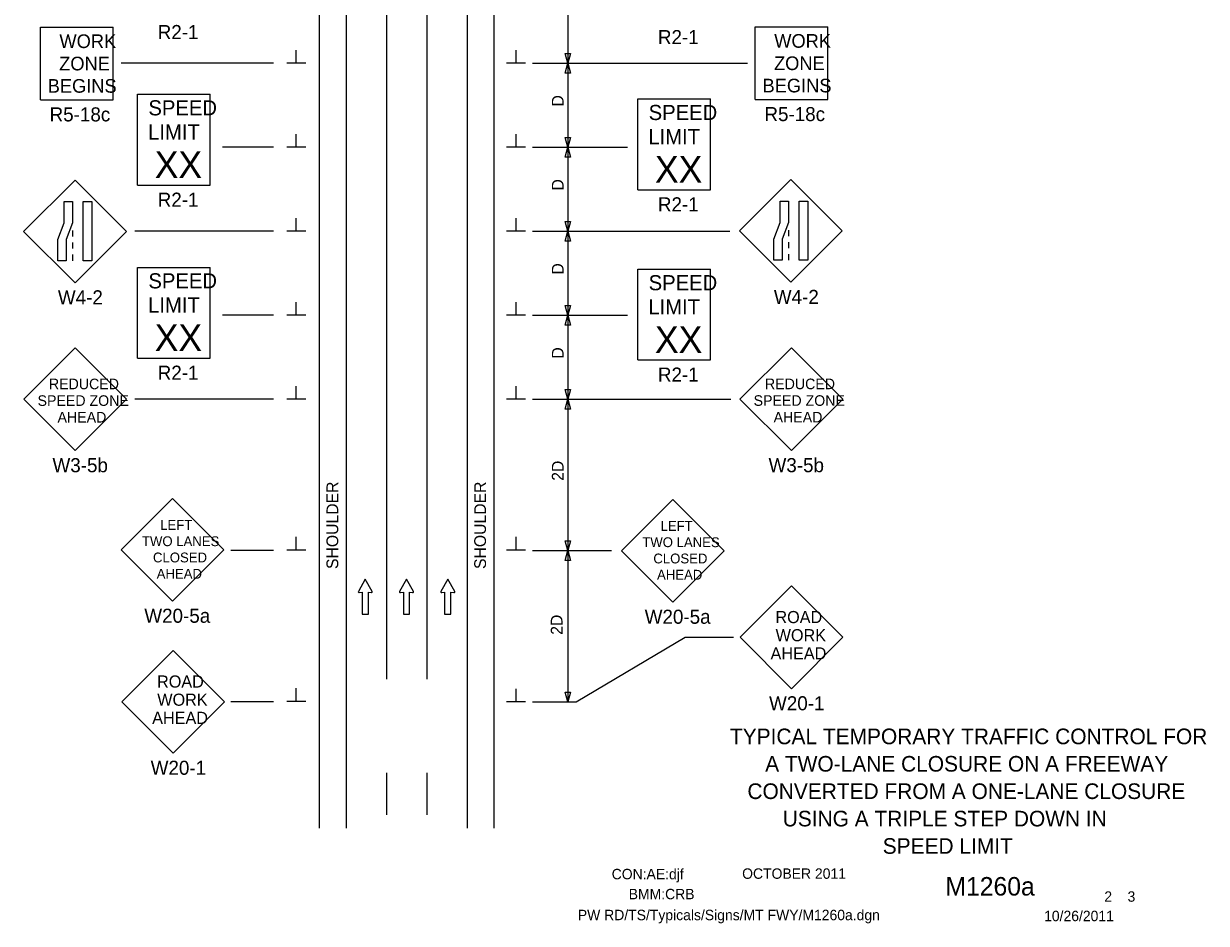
# Model space of a CAD drawing. Extents: x 16503 to 19508, y 5728 to 6974.
# Drawn here: x 17770 to 18473, y 5932 to 6467 of the extents above; entities that cross this region are included whole.
import ezdxf

# ---------------------------------------------------------------- set-up
doc = ezdxf.new("R2010")
doc.units = 0
for name, color, linetype in [('ALI_LEGAL_EX', 7, 'Continuous'), ('BORDER', 7, 'Continuous'), ('BORDER_SIGNAL_WO', 7, 'Continuous'), ('MT_SCRATCH_LEVEL_E', 7, 'Continuous'), ('PAVT_EDGE_EX', 7, 'Continuous'), ('TRAFFIC_SIGNS_PR', 7, 'Continuous'), ('TYPICAL_TEXT_DIMEN_PR', 7, 'Continuous')]:
    doc.layers.add(name, color=color, linetype=linetype)

msp = doc.modelspace()

# ---------------------------------------------------------------- linework, layer by layer
at = {"layer": 'ALI_LEGAL_EX'}
for p, q in [((17985.63, 6921.33), (17985.63, 6077.19)), ((18009.63, 6921.33), (18009.63, 6077.19))]:
    msp.add_line(p, q, dxfattribs=at)
for points in [[(17985.63, 6421.33), (17985.63, 6396.33)], [(18009.63, 6421.33), (18009.63, 6396.33)], [(17985.63, 6321.33), (17985.63, 6296.33)], [(18009.63, 6321.33), (18009.63, 6296.33)], [(17985.63, 6221.33), (17985.63, 6196.33)], [(18009.63, 6221.33), (18009.63, 6196.33)], [(17985.63, 6121.33), (17985.63, 6096.33)], [(18009.63, 6121.33), (18009.63, 6096.33)], [(17985.63, 6021.33), (17985.63, 5996.33)], [(18009.63, 6021.33), (18009.63, 5996.33)]]:
    msp.add_lwpolyline(points, dxfattribs=at)
at = {"layer": 'MT_SCRATCH_LEVEL_E'}
for p, q in [((17973.07, 6136.57), (17968.96, 6129.33)), ((17977.22, 6129.33), (17973.07, 6136.57)), ((17997.6, 6136.57), (17993.49, 6129.33)), ((18001.75, 6129.33), (17997.6, 6136.57)), ((18022.16, 6136.57), (18018.05, 6129.33)), ((18026.31, 6129.33), (18022.16, 6136.57)), ((17969.44, 6128.65), (17971.22, 6128.96)), ((17971.22, 6128.96), (17971.22, 6115.71)), ((17974.96, 6115.71), (17974.96, 6128.96)), ((17974.96, 6128.96), (17976.74, 6128.65)), ((17993.97, 6128.65), (17995.75, 6128.96)), ((17995.75, 6128.96), (17995.75, 6115.71)), ((17999.49, 6115.71), (17999.49, 6128.96)), ((17999.49, 6128.96), (18001.27, 6128.65)), ((18018.53, 6128.65), (18020.31, 6128.96)), ((18020.31, 6128.96), (18020.31, 6115.71)), ((18024.05, 6115.71), (18024.05, 6128.96)), ((18024.05, 6128.96), (18025.83, 6128.65)), ((17971.22, 6115.71), (17974.96, 6115.71)), ((17995.75, 6115.71), (17999.49, 6115.71)), ((18020.31, 6115.71), (18024.05, 6115.71))]:
    msp.add_line(p, q, dxfattribs=at)
for centre, start, end in [((17969.37, 6129.11), 150.42484, 279.96381), ((17976.81, 6129.11), 260.03619, 29.77312), ((17993.9, 6129.11), 150.42484, 279.96381), ((18001.34, 6129.11), 260.03619, 29.77312), ((18018.46, 6129.11), 150.42484, 279.96381), ((18025.9, 6129.11), 260.03619, 29.77312)]:
    msp.add_arc(centre, 0.463, start, end, dxfattribs=at)
at = {"layer": 'PAVT_EDGE_EX'}
for p, q in [((17945.63, 6921.33), (17945.63, 5988.51)), ((17961.63, 6921.33), (17961.63, 5988.51)), ((18033.63, 6921.33), (18033.63, 5988.51)), ((18049.63, 6921.33), (18049.63, 5988.51))]:
    msp.add_line(p, q, dxfattribs=at)
at = {"layer": 'TRAFFIC_SIGNS_PR'}
for p, q in [((17779.88, 6421.85), (17779.88, 6465.05)), ((17779.88, 6465.05), (17823.08, 6465.05)), ((17823.08, 6421.85), (17823.08, 6465.05)), ((18205.13, 6422.03), (18205.13, 6465.23)), ((18205.13, 6465.23), (18248.33, 6465.23)), ((18248.33, 6422.03), (18248.33, 6465.23)), ((17837.58, 6425.1), (17880.78, 6425.1)), ((17837.58, 6371.1), (17837.58, 6425.1)), ((17880.78, 6371.1), (17880.78, 6425.1)), ((17779.88, 6421.85), (17823.08, 6421.85)), ((18135.18, 6422.33), (18178.38, 6422.33)), ((18135.18, 6368.33), (18135.18, 6422.33)), ((18178.38, 6368.33), (18178.38, 6422.33)), ((18205.13, 6422.03), (18248.33, 6422.03)), ((17800.4, 6374.1), (17769.85, 6343.55)), ((17830.95, 6343.55), (17800.4, 6374.1)), ((17837.58, 6371.1), (17880.78, 6371.1)), ((18135.18, 6368.33), (18178.38, 6368.33)), ((18226.32, 6374.35), (18195.77, 6343.8)), ((18256.86, 6343.8), (18226.32, 6374.35)), ((17769.85, 6343.55), (17800.4, 6313)), ((17799, 6344.1), (17799, 6340.5)), ((17800.4, 6313), (17830.95, 6343.55)), ((18195.77, 6343.8), (18226.32, 6313.26)), ((18224.91, 6344.35), (18224.91, 6340.75)), ((18226.32, 6313.26), (18256.86, 6343.8)), ((17799, 6336.9), (17799, 6333.3)), ((18224.91, 6337.15), (18224.91, 6333.55)), ((17799, 6329.7), (17799, 6326.1)), ((18224.91, 6329.95), (18224.91, 6326.35)), ((17837.58, 6322.16), (17880.78, 6322.16)), ((17837.58, 6268.16), (17837.58, 6322.16)), ((17880.78, 6268.16), (17880.78, 6322.16)), ((18135.18, 6321.04), (18178.38, 6321.04)), ((18135.18, 6267.04), (18135.18, 6321.04)), ((18178.38, 6267.04), (18178.38, 6321.04)), ((17800.58, 6274.21), (17770.03, 6243.66)), ((17831.12, 6243.66), (17800.58, 6274.21)), ((18226.56, 6274.24), (18196.01, 6243.69)), ((18257.11, 6243.69), (18226.56, 6274.24)), ((17837.58, 6268.16), (17880.78, 6268.16)), ((18135.18, 6267.04), (18178.38, 6267.04)), ((17770.03, 6243.66), (17800.58, 6213.12)), ((17800.58, 6213.12), (17831.12, 6243.66)), ((18196.01, 6243.69), (18226.56, 6213.15)), ((18226.56, 6213.15), (18257.11, 6243.69)), ((17858.36, 6184.64), (17827.82, 6154.1)), ((17888.91, 6154.1), (17858.36, 6184.64)), ((18156.04, 6184.05), (18125.49, 6153.5)), ((18186.58, 6153.5), (18156.04, 6184.05)), ((17827.82, 6154.1), (17858.36, 6123.55)), ((17858.36, 6123.55), (17888.91, 6154.1)), ((18125.49, 6153.5), (18156.04, 6122.95)), ((18156.04, 6122.95), (18186.58, 6153.5)), ((18226.61, 6132.56), (18196.07, 6102.02)), ((18257.16, 6102.02), (18226.61, 6132.56)), ((18196.07, 6102.02), (18226.61, 6071.47)), ((18226.61, 6071.47), (18257.16, 6102.02)), ((17858.74, 6094.19), (17828.19, 6063.64)), ((17889.29, 6063.64), (17858.74, 6094.19)), ((17828.19, 6063.64), (17858.74, 6033.09)), ((17858.74, 6033.09), (17889.29, 6063.64))]:
    msp.add_line(p, q, dxfattribs=at)
for points in [[(17799, 6361.25), (17799, 6348.67), (17795.23, 6338.68), (17795.23, 6326.1), (17790.18, 6326.1), (17790.18, 6338.68), (17793.94, 6348.67), (17793.94, 6361.25)], [(17810.4, 6361.25), (17810.4, 6326.1), (17805.34, 6326.1), (17805.34, 6361.25)], [(18224.91, 6361.51), (18224.91, 6348.93), (18221.15, 6338.93), (18221.15, 6326.35), (18216.1, 6326.35), (18216.1, 6338.93), (18219.86, 6348.93), (18219.86, 6361.51)], [(18236.32, 6361.51), (18236.32, 6326.35), (18231.26, 6326.35), (18231.26, 6361.51)]]:
    msp.add_lwpolyline(points, close=True, dxfattribs=at)
at = {"layer": 'TYPICAL_TEXT_DIMEN_PR'}
for p, q in [((18093.63, 6493.63), (18093.63, 6443.63)), ((17932.02, 6443.63), (17932.02, 6451.41)), ((18062.76, 6443.63), (18062.76, 6451.41)), ((18093.63, 6443.63), (18092.06, 6449.49)), ((18092.06, 6449.49), (18093.63, 6449.49)), ((18093.63, 6449.49), (18095.2, 6449.49)), ((18095.2, 6449.49), (18093.63, 6443.63)), ((17918.58, 6443.63), (17827.86, 6443.63)), ((17937.64, 6443.63), (17926.39, 6443.63)), ((18068.38, 6443.63), (18057.13, 6443.63)), ((18072.63, 6443.63), (18200.38, 6443.63)), ((18092.06, 6437.77), (18093.63, 6443.63)), ((18093.63, 6443.63), (18095.2, 6437.77)), ((18093.63, 6443.63), (18093.63, 6393.63)), ((18093.63, 6437.77), (18092.06, 6437.77)), ((18095.2, 6437.77), (18093.63, 6437.77)), ((17932.02, 6393.63), (17932.02, 6401.41)), ((18062.76, 6393.63), (18062.76, 6401.41)), ((18093.63, 6393.63), (18092.06, 6399.49)), ((18092.06, 6399.49), (18093.63, 6399.49)), ((18093.63, 6399.49), (18095.2, 6399.49)), ((18095.2, 6399.49), (18093.63, 6393.63)), ((17918.58, 6393.63), (17888.17, 6393.63)), ((17937.64, 6393.63), (17926.39, 6393.63)), ((18068.38, 6393.63), (18057.13, 6393.63)), ((18072.63, 6393.63), (18129.14, 6393.63)), ((18092.06, 6387.77), (18093.63, 6393.63)), ((18093.63, 6393.63), (18093.63, 6343.63)), ((18093.63, 6393.63), (18095.2, 6387.77)), ((18093.63, 6387.77), (18092.06, 6387.77)), ((18095.2, 6387.77), (18093.63, 6387.77)), ((17932.02, 6343.63), (17932.02, 6351.41)), ((18062.76, 6343.63), (18062.76, 6351.41)), ((18093.63, 6343.63), (18092.06, 6349.49)), ((18092.06, 6349.49), (18093.63, 6349.49)), ((18093.63, 6349.49), (18095.2, 6349.49)), ((18095.2, 6349.49), (18093.63, 6343.63)), ((17918.58, 6343.63), (17836, 6343.63)), ((17937.64, 6343.63), (17926.39, 6343.63)), ((18068.38, 6343.63), (18057.13, 6343.63)), ((18072.63, 6343.63), (18189.96, 6343.63)), ((18092.06, 6337.77), (18093.63, 6343.63)), ((18093.63, 6343.63), (18093.63, 6293.63)), ((18093.63, 6343.63), (18095.2, 6337.77)), ((18093.63, 6337.77), (18092.06, 6337.77)), ((18095.2, 6337.77), (18093.63, 6337.77)), ((17932.02, 6293.63), (17932.02, 6301.41)), ((18062.76, 6293.63), (18062.76, 6301.41)), ((18093.63, 6293.63), (18092.06, 6299.49)), ((18092.06, 6299.49), (18093.63, 6299.49)), ((18093.63, 6299.49), (18095.2, 6299.49)), ((18095.2, 6299.49), (18093.63, 6293.63)), ((17918.58, 6293.63), (17888.17, 6293.63)), ((17937.64, 6293.63), (17926.39, 6293.63)), ((18068.38, 6293.63), (18057.13, 6293.63)), ((18072.63, 6293.63), (18129.14, 6293.63)), ((18092.06, 6287.77), (18093.63, 6293.63)), ((18093.63, 6293.63), (18093.63, 6243.63)), ((18093.63, 6293.63), (18095.2, 6287.77)), ((18093.63, 6287.77), (18092.06, 6287.77)), ((18095.2, 6287.77), (18093.63, 6287.77)), ((17932.02, 6243.63), (17932.02, 6251.41)), ((18062.76, 6243.63), (18062.76, 6251.41)), ((18093.63, 6243.63), (18092.06, 6249.49)), ((18092.06, 6249.49), (18093.63, 6249.49)), ((18093.63, 6249.49), (18095.2, 6249.49)), ((18095.2, 6249.49), (18093.63, 6243.63)), ((17918.58, 6243.63), (17836, 6243.63)), ((17937.64, 6243.63), (17926.39, 6243.63)), ((18068.38, 6243.63), (18057.13, 6243.63)), ((18072.63, 6243.63), (18190.65, 6243.63)), ((18092.06, 6237.77), (18093.63, 6243.63)), ((18093.63, 6243.63), (18093.63, 6153.63)), ((18093.63, 6243.63), (18095.2, 6237.77)), ((18093.63, 6237.77), (18092.06, 6237.77)), ((18095.2, 6237.77), (18093.63, 6237.77)), ((17932.02, 6153.95), (17932.02, 6161.74)), ((18062.76, 6153.95), (18062.76, 6161.74)), ((18093.63, 6153.63), (18092.06, 6159.49)), ((18092.06, 6159.49), (18093.63, 6159.49)), ((18093.63, 6159.49), (18095.2, 6159.49)), ((18095.2, 6159.49), (18093.63, 6153.63)), ((17918.58, 6153.63), (17893.02, 6153.63)), ((17937.64, 6153.95), (17926.39, 6153.95)), ((18068.38, 6153.95), (18057.13, 6153.95)), ((18072.63, 6153.63), (18119.59, 6153.63)), ((18092.06, 6147.77), (18093.63, 6153.63)), ((18093.63, 6153.63), (18093.63, 6063.63)), ((18093.63, 6153.63), (18095.2, 6147.77)), ((18093.63, 6147.77), (18092.06, 6147.77)), ((18095.2, 6147.77), (18093.63, 6147.77)), ((18098.63, 6063.63), (18163.48, 6102.13)), ((18163.48, 6102.13), (18192.05, 6102.13)), ((17932.02, 6063.9), (17932.02, 6071.68)), ((18062.76, 6063.63), (18062.76, 6071.41)), ((18093.63, 6063.63), (18092.06, 6069.49)), ((18092.06, 6069.49), (18093.63, 6069.49)), ((18093.63, 6069.49), (18095.2, 6069.49)), ((18095.2, 6069.49), (18093.63, 6063.63)), ((17918.58, 6063.63), (17893.02, 6063.63)), ((17937.64, 6063.9), (17926.39, 6063.9)), ((18068.38, 6063.63), (18057.13, 6063.63)), ((18072.63, 6063.63), (18098.63, 6063.63))]:
    msp.add_line(p, q, dxfattribs=at)

# ---------------------------------------------------------------- texts
at = {"layer": 'BORDER'}
for s, p in [('TYPICAL TEMPORARY TRAFFIC CONTROL FOR', (18190.04, 6038.42)), ('A TWO-LANE CLOSURE ON A FREEWAY', (18210.99, 6022.12)), ('CONVERTED FROM A ONE-LANE CLOSURE ', (18200.42, 6005.82)), ('USING A TRIPLE STEP DOWN IN ', (18221.42, 5989.52)), ('SPEED LIMIT', (18280.92, 5973.22))]:
    msp.add_text(s, height=9.3, dxfattribs=at).set_placement(p)
at = {"layer": 'BORDER_SIGNAL_WO'}
for s, height, p in [('CON:AE:djf  ', 6.2, (18119.69, 5958.06)), ('    OCTOBER 2011    ', 6.2, (18188.08, 5958.34)), ('    M1260a   ', 11, (18301.86, 5948.38)), ('BMM:CRB   ', 6.2, (18129.81, 5946.17)), (' 2    3 ', 6.2, (18410.45, 5944.7)), ('PW RD/TS/Typicals/Signs/MT FWY/M1260a.dgn      ', 6.2, (18099.55, 5933.71)), ('10/26/2011    ', 6.2, (18376.93, 5933.13))]:
    msp.add_text(s, height=height, dxfattribs=at).set_placement(p)
at = {"layer": 'TRAFFIC_SIGNS_PR'}
for s, height, p in [('R2-1', 8.37, (17849.6, 6457.97)), ('WORK', 8.119, (17791.13, 6452.64)), ('R2-1', 8.37, (18147.19, 6454.97)), ('WORK', 8.119, (18216.38, 6452.82)), ('ZONE', 8.119, (17790.99, 6439.35)), ('ZONE', 8.119, (18216.25, 6439.53)), ('BEGINS', 8.119, (17784.16, 6426.06)), ('BEGINS', 8.119, (18209.42, 6426.25)), ('R5-18c', 8.37, (17785.29, 6408.98)), ('SPEED', 9, (17844.07, 6412.57)), ('SPEED', 9, (18141.67, 6409.8)), ('R5-18c', 8.37, (18210.54, 6409.16)), ('LIMIT', 9, (17843.89, 6398.17)), ('LIMIT', 9, (18141.49, 6395.4)), ('XX', 15.785, (17847.84, 6375.33)), ('XX', 15.785, (18145.43, 6372.56)), ('R2-1', 8.37, (17849.6, 6358.23)), ('R2-1', 8.37, (18147.19, 6355.46)), ('SPEED', 9, (17844.07, 6309.63)), ('SPEED', 9, (18141.67, 6308.51)), ('W4-2', 8.37, (17790.23, 6300.13)), ('LIMIT', 9, (17843.89, 6295.23)), ('W4-2', 8.37, (18216.15, 6300.39)), ('LIMIT', 9, (18141.49, 6294.11)), ('XX', 15.785, (17847.84, 6272.39)), ('XX', 15.785, (18145.43, 6271.27)), ('R2-1', 8.37, (17849.6, 6255.29)), ('R2-1', 8.37, (18147.19, 6254.17)), ('REDUCED', 6.3, (17784.89, 6249.63)), ('REDUCED', 6.3, (18210.88, 6249.66)), ('SPEED ZONE', 6.3, (17778.13, 6239.73)), ('SPEED ZONE', 6.3, (18204.12, 6239.76)), ('AHEAD', 6.3, (17790.01, 6229.83)), ('AHEAD', 6.3, (18216, 6229.86)), ('W3-5b', 8.37, (17787.02, 6200.25)), ('W3-5b', 8.37, (18213.01, 6200.28)), ('LEFT', 5.85, (17851.09, 6165.95)), ('LEFT', 5.85, (18148.77, 6165.35)), ('TWO LANES', 5.85, (17840.21, 6156.27)), ('TWO LANES', 5.85, (18137.88, 6155.68)), ('CLOSED', 5.85, (17846.79, 6146.6)), ('CLOSED', 5.85, (18144.46, 6146)), ('AHEAD', 5.85, (17848.98, 6136.92)), ('AHEAD', 5.85, (18146.65, 6136.33)), ('W20-5a', 8.37, (17841.65, 6110.68)), ('W20-5a', 8.37, (18139.32, 6110.09)), ('ROAD', 7.2, (18217.1, 6110.49)), ('WORK', 7.2, (18217.22, 6099.69)), ('AHEAD', 7.2, (18214.19, 6088.89)), ('ROAD', 7.2, (17849.22, 6072.12)), ('WORK', 7.2, (17849.35, 6061.32)), ('W20-1', 8.37, (18213.3, 6058.6)), ('AHEAD', 7.2, (17846.32, 6050.52)), ('W20-1', 8.37, (17845.43, 6020.22))]:
    msp.add_text(s, height=height, dxfattribs=at).set_placement(p)
at = {"layer": 'TYPICAL_TEXT_DIMEN_PR'}
for s, p in [('D', (18091.08, 6417.85)), ('D', (18091.08, 6367.85)), ('D', (18091.08, 6317.85)), ('D', (18091.08, 6267.85)), ('2D', (18091.08, 6195.15)), ('SHOULDER', (17957.01, 6142.68)), ('SHOULDER', (18044.91, 6142.68)), ('2D', (18090.43, 6103.54))]:
    msp.add_text(s, height=7, rotation=90, dxfattribs=at).set_placement(p)

doc.saveas('drawing.dxf')
